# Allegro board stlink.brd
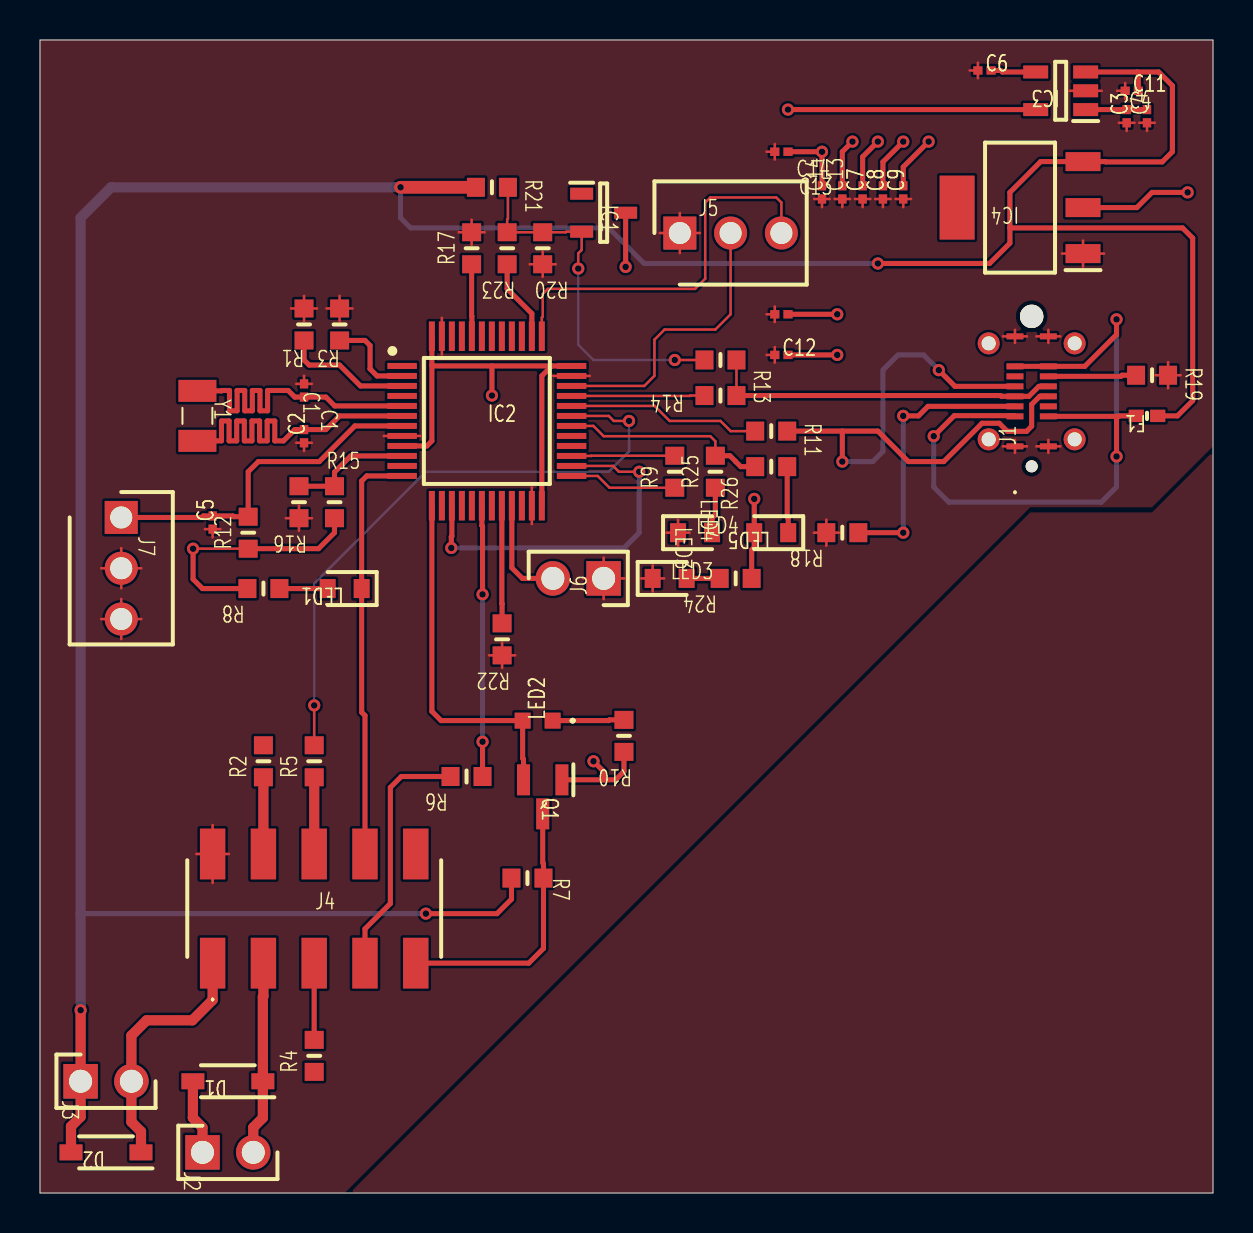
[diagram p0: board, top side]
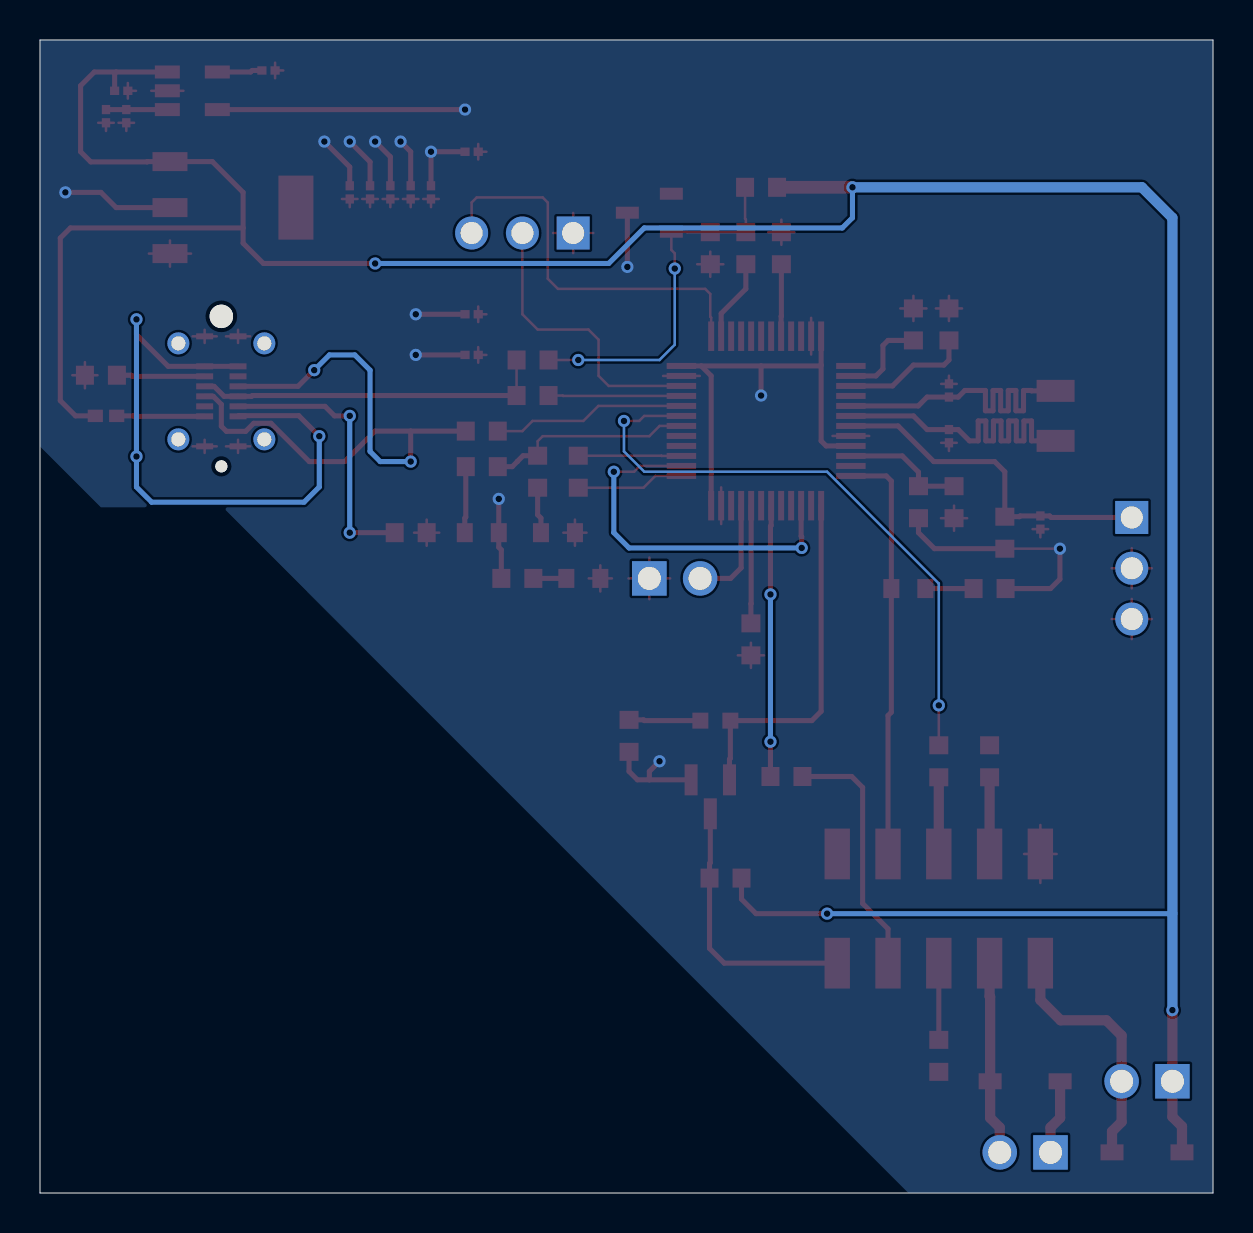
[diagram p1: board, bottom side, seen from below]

Outline 58.67 x 57.66 mm; copper layers: TOP, BOTTOM. Coordinates in mm from the lower left corner of the outline.
Outline path: 0,57.66 0,0 58.67,0 58.67,57.66 0,57.66

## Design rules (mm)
constraint set DEFAULT: min track width 0.127
net group DN: nets DN USB_DM
net group RESET: nets N06427 RESET
net group SWO: nets N06435 SWO
net group +5V: nets DP N06887 N27475 USB_DP
net group LED_LINK: nets LED_LINK N09917 N09921

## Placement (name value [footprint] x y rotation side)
C1  20p  [CAPC0603X33N]  13.21 40.13 270 top
C2  20p  [CAPC0603X33N]  13.21 37.85 90 top
C3  1u  [CAPC0603X33N]  54.36 53.85 90 top
C4  100n  [CAPC0603X33N]  55.37 53.85 90 top
C5  100n  [CAPC0603X33N]  8.64 33.53 90 top
C6  22n  [CAPC0603X33N]  47.24 56.13 0 top
C7  10u  [CAPC0603X33N]  41.15 50.04 90 top
C8  100n  [CAPC0603X33N]  42.16 50.04 90 top
C9  20p  [CAPC0603X33N]  43.18 50.04 90 top
C10  20p  [CAPC0603X33N]  37.08 43.94 0 top
C11  20p  [CAPC0603X33N]  54.61 55.12 0 top
C12  100n  [CAPC0603X33N]  37.08 41.91 0 top
C13  100n  [CAPC0603X33N]  40.13 50.04 90 top
C14  100n  [CAPC0603X33N]  39.12 50.04 90 top
C15  100n  [CAPC0603X33N]  37.08 52.07 0 top
D1  MBR0520LT3G  [SOD3716X135N]  9.4 5.59 180 top
D2  MBR0520LT3G  [SOD3716X135N]  3.3 2.03 180 top
F1  SF-0402F050-2  [FUSC1005X40N]  55.37 38.86 180 top
IC1  MMS9013-L-TP  [SOT95P237X125-3N]  28.19 49.02 0 top
IC2  STM32F103CBT6  [QFP50P900X900X160-48N]  22.35 38.61 0 top
IC3  RT9193-33GB  [SOT94P279X130-5N]  51.05 55.12 180 top
IC4  LM1117MPX-33NOPB  [SOT230P700X180-4N]  49.02 49.28 180 top
J1  219320-0001  [2193200001]  48.77 37.34 90 top
J2  JUMPER  [HDRV2W67P254_2X1_254X483X858P]  8.13 2.03 270 top
J3  JUMPER  [HDRV2W67P254_2X1_254X483X858P]  2.03 5.59 270 top
J4  95278-401A10LF  [95278401A10LF]  13.72 14.22 0 top
J5  69167-103  [SHDR3W64P0X254_1X3_762X516X980P]  32 48.01 0 top
J6  JUMPER  [HDRV2W67P254_2X1_254X483X858P]  28.19 30.73 90 top
J7  69167-103  [SHDR3W64P0X254_1X3_762X516X980P]  4.06 33.78 270 top
LED1  SM0603GCL  [LEDC1608X60N]  15.24 30.23 180 top
LED2  -  [SM0603SRC]  24.89 23.62 90 top
LED3  SM0603GCL  [LEDC1608X60N]  31.5 30.73 0 top
LED4  SM0603GCL  [LEDC1608X60N]  32.77 33.02 0 top
LED5  SM0603GCL  [LEDC1608X60N]  36.58 33.02 180 top
Q1  2N7002  [SOT96P240X120-3N]  25.15 19.81 270 top
R1  10K  [RESC1608X55N]  13.21 43.43 270 top
R2  22  [RESC1608X55N]  11.18 21.59 90 top
R3  10K  [RESC1608X55N]  14.99 43.43 270 top
R4  22  [RESC1608X55N]  13.72 6.86 90 top
R5  22  [RESC1608X55N]  13.72 21.59 90 top
R6  22  [RESC1608X55N]  21.34 20.83 180 top
R7  1K  [RESC1608X55N]  24.38 15.75 0 top
R8  1K  [RESC1608X55N]  11.18 30.23 180 top
R9  100  [RESC1608X55N]  31.75 36.07 90 top
R10  1K  [RESC1608X55N]  29.21 22.86 270 top
R11  0  [RESC1608X55N]  36.58 38.1 0 top
R12  100K  [RESC1608X55N]  10.41 33.02 90 top
R13  0  [RESC1608X55N]  34.04 39.88 0 top
R14  1K5  [RESC1608X55N]  34.04 41.66 180 top
R15  4K7  [RESC1608X55N]  14.73 34.54 90 top
R16  4K7  [RESC1608X55N]  12.95 34.54 270 top
R17  10K  [RESC1608X55N]  21.59 47.24 90 top
R18  5.1K  [RESC1608X55N]  40.13 33.02 180 top
R19  5.1K  [RESC1608X55N]  55.63 40.89 0 top
R20  36K  [RESC1608X55N]  25.15 47.24 270 top
R21  10K  [RESC1608X55N]  22.61 50.29 0 top
R22  10K  [RESC1608X55N]  23.11 27.69 270 top
R23  100  [RESC1608X55N]  23.37 47.24 270 top
R24  10K  [RESC1608X55N]  34.8 30.73 180 top
R25  1K  [RESC1608X55N]  33.78 36.07 90 top
R26  1K  [RESC1608X55N]  36.58 36.32 180 top
Y1  ABS07-32  [ABS07]  7.87 38.86 270 top

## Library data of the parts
C1-C15 = GRM033D70E105ME15D
D1 D2 = MBR0520LT3G
F1 = SF-0402F050-2
IC1 = MMS9013-L-TP
IC2 = STM32F103CBT6
IC3 = RT9193-33GB
IC4 = LM1117MPX-33NOPB
J1 = 219320-0001
J2 J3 J6 = 67996-100HLF
J4 = 95278-401A10LF
J5 J7 = 69167-103
LED1 LED3-LED5 = SM0603GCL
LED2 = SM0603SRC
Q1 = 2N7002
R1-R26 = CR0603-F_-1R00ELF
Y1 = ABS07-32.768KHZ-T

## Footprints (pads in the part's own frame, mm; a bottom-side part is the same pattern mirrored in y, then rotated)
95278401A10LF
  rect 1.27x2.54 smd: 1(-5.08,-2.73) 2(-5.08,2.73) 3(-2.54,-2.73) 4(-2.54,2.73) 5(0,-2.73) 6(0,2.73) 7(2.54,-2.73) 8(2.54,2.73) 9(5.08,-2.73) 10(5.08,2.73)
2193200001
  round 0.6 hole 0.6 unplated: (-1,-0.835)
  round 1.17 hole 1.17 unplated: (6.5,-0.835)
  rect 0.3x0.85 smd: A1(0,0) A4(1.5,0) A5(2,0) A6(2.5,0) A7(3,0) A8(3.5,0) A9(4,0) A12(5.5,0) B1(5.5,-1.67) B4(4,-1.67) B5(3.5,-1.67) B6(3,-1.67) B7(2.5,-1.67) B8(2,-1.67) B9(1.5,-1.67) B12(0,-1.67)
  round 1.1 hole 0.7: MH3(0.35,1.315) MH4(5.15,1.315) MH5(5.15,-2.985) MH6(0.35,-2.985)
ABS07
  rect 1.1x1.9 smd: 1(-1.25,0) 2(1.25,0)
CAPC0603X33N
  rect 0.46x0.42 smd: 1(-0.33,0) 2(0.33,0)
FUSC1005X40N
  rect 0.76x0.62 smd: 1(-0.535,0) 2(0.535,0)
HDRV2W67P254_2X1_254X483X858P
  rect 1.725x1.725 hole 1.15: 1(0,0)
  round 1.725 hole 1.15: 2(0,2.54)
LEDC1608X60N
  rect 0.8x0.95 smd: 1(-0.85,0) 2(0.85,0)
QFP50P900X900X160-48N
  rect 1.475x0.3 smd: 1(-4.238,2.75) 2(-4.238,2.25) 3(-4.238,1.75) 4(-4.238,1.25) 5(-4.238,0.75) 6(-4.238,0.25) 7(-4.238,-0.25) 8(-4.238,-0.75) 9(-4.238,-1.25) 10(-4.238,-1.75) 11(-4.238,-2.25) 12(-4.238,-2.75) 25(4.238,-2.75) 26(4.238,-2.25) 27(4.238,-1.75) 28(4.238,-1.25) 29(4.238,-0.75) 30(4.238,-0.25) 31(4.238,0.25) 32(4.238,0.75) 33(4.238,1.25) 34(4.238,1.75) 35(4.238,2.25) 36(4.238,2.75)
  rect 0.3x1.475 smd: 13(-2.75,-4.238) 14(-2.25,-4.238) 15(-1.75,-4.238) 16(-1.25,-4.238) 17(-0.75,-4.238) 18(-0.25,-4.238) 19(0.25,-4.238) 20(0.75,-4.238) 21(1.25,-4.238) 22(1.75,-4.238) 23(2.25,-4.238) 24(2.75,-4.238) 37(2.75,4.238) 38(2.25,4.238) 39(1.75,4.238) 40(1.25,4.238) 41(0.75,4.238) 42(0.25,4.238) 43(-0.25,4.238) 44(-0.75,4.238) 45(-1.25,4.238) 46(-1.75,4.238) 47(-2.25,4.238) 48(-2.75,4.238)
RESC1608X55N
  rect 0.9x0.95 smd: 1(-0.8,0) 2(0.8,0)
SHDR3W64P0X254_1X3_762X516X980P
  rect 1.65x1.65 hole 1.1: 1(0,0)
  round 1.65 hole 1.1: 2(2.54,0) 3(5.08,0)
SM0603SRC
  rect 0.8x0.8 smd: 1(0,-0.75) 2(0,0.75)
SOD3716X135N
  rect 1.15x0.8 smd: 1(-1.75,0) 2(1.75,0)
SOT94P279X130-5N
  rect 1.25x0.65 smd: 1(-1.25,0.94) 2(-1.25,0) 3(-1.25,-0.94) 4(1.25,-0.94) 5(1.25,0.94)
SOT95P237X125-3N
  rect 1.15x0.6 smd: 1(-1.1,0.95) 2(-1.1,-0.95) 3(1.1,0)
SOT96P240X120-3N
  rect 1.55x0.65 smd: 1(-0.85,0.96) 2(-0.85,-0.96) 3(0.85,0)
SOT230P700X180-4N
  rect 1.75x0.95 smd: 1(-3.15,2.3) 2(-3.15,0) 3(-3.15,-2.3)
  rect 1.75x3.2 smd: 4(3.15,0)

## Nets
+3V3: C7.2 C8.2 C9.2 C10.2 C12.2 C13.2 C14.2 C15.2 IC1.3 IC2.9 IC2.24 IC2.36 IC2.48 IC3.5(\VOUT\) IC4.2 LED5.2 Q1.1 R8.2 R10.2 R12.1 R15.1 R24.1
+5V: C11.2 D2.2 F1.1 IC3.3 IC4.3 J3.1 R7.1 R21.1
GND: C1.1 C2.1 C3.1 C4.1 C5.1 C6.1 C7.1 C8.1 C9.1 C10.1 C11.1 C12.1 C13.1 C14.1 C15.1 IC2.8 IC2.23 IC2.35 IC2.47(\VSS_3\) IC3.2 IC4.1 J1.A1 J1.A12 J1.B1 J1.B12 J4.2 J5.1 J6.1 J7.2 J7.3 LED3.1(\K\) LED4.1(\K\) R1.1 R3.1 R16.2 R17.2 R18.2 R19.2 R20.2 R22.2
VBAT: IC2.1
BOOT_0: IC2.44 R17.1
BOOT_1: IC2.20 R22.1
DN: J1.A7 J1.B7 R11.2
DP: J1.A6(\[DP1\) J1.B6 R13.2 R14.1
FUSE: F1.2 J1.A4 J1.A9 J1.B4 J1.B9
LED_LINK: IC2.30 R25.2 R26.2
PA0: IC2.10 R15.2 R16.1
RESET: IC2.18 R6.1
RST: C5.2 IC2.7 J7.1 R12.2
RX: IC2.13 LED2.2(\K\) Q1.2(\S\)
SWCLK: IC2.15 IC2.26 R4.1
SWCLK_IN: IC2.37 J5.3
SWDIO: IC2.25 R2.2 R9.1
SWDIO_IN: IC2.34 J5.2
SWO: IC2.31 R5.2
TX: IC2.12 J4.8 LED1.1(\K\)
USB_DM: IC2.32 R11.1
USB_DP: IC2.33 R13.1
USB_RENUM: IC2.38 R23.2
N00368: IC2.2 R3.2
N00410: IC2.3 R1.2
N00775: C1.2 IC2.5 Y1.1
N00782: C2.2 IC2.6 Y1.2
N01382: IC2.21 J6.2
N02734: IC2.27 R9.2
N04880: D2.1(\K\) J3.2 J4.1
N05760: D1.2 J2.1
N05764: D1.1(\K\) J2.2 J4.3
N06309: J4.4 R2.1
N06427: J4.7 R6.2
N06431: J4.5 R4.2
N06435: J4.6 R5.1
N06707: LED1.2 R8.1
N06887: J4.9 Q1.3 R7.2
N07180: LED2.1 R10.1
N08768: LED3.2 R24.2
N09917: LED4.2 R25.1
N09921: LED5.1(\K\) R26.1
N11997: C3.2 C4.2 IC3.1
N13004: C6.2 IC3.4
N27475: IC1.2(\E\) R14.2 R20.1 R21.2 R23.1
N30478: J1.B5 R19.1
N30510: J1.A5 R18.1

Pads without a net: IC1 1; IC2 4 11 14 16 17 19 22 28 29 39 40 41 42 43 45 46; IC4 4; J1 A8 B8 MH3 MH4 MH5 MH6; J4 10

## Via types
v1: diameter 0.61, hole 0.33, TOP to BOTTOM, 33 vias

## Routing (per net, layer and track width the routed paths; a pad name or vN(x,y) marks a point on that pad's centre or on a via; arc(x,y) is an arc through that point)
+3V3: length 83.8
  TOP w0.127: R12.1 v1(7.66,32.22)
  TOP w0.254: C7.2 41.15,51.82 v1(41.91,52.58) ; IC2.24 25.1,40.86 25.6,41.36 ; 22.61,41.36 v1(22.61,39.88) ; 22.61,41.36 25.6,41.36 ; 22.61,41.36 19.65,41.36 19.6,41.4 ; 25.6,41.36 IC2.36 ; 28.19,20.66 28.19,21.08 v1(27.69,21.59) ; 28.19,20.66 Q1.1 ; 28.19,20.66 28.79,20.66 29.21,21.08 R10.2 ; IC4.2 54.86,49.28 55.63,50.04 v1(57.4,50.04) ; v1(43.18,52.58) 42.16,51.56 C8.2 ; IC3.5 v1(37.41,54.18) ; IC1.3 v1(29.29,46.31) ; R24.1 35.6,32.16 35.73,32.29 LED5.2 v1(35.73,34.71) ; v1(44.45,52.58) 43.18,51.31 C9.2 ; R8.2 8.13,30.23 7.66,30.7 v1(7.66,32.22) ; R12.1 13.93,32.22 14.73,33.02 R15.1 ; C10.2 v1(39.88,43.94) ; 19.6,41.4 19.6,37.61 19.35,37.36 IC2.9 ; 19.6,41.4 IC2.48 ; C13.2 40.13,52.07 v1(40.64,52.58) ; C12.2 v1(39.88,41.91) ; C14.2 v1(39.12,52.07) C15.2
+5V: length 163.6
  TOP w0.254: 54.86,56.06 55.96,56.06 56.64,55.37 56.64,52.07 56.13,51.56 53.32,51.56 53.3,51.58 IC4.3 50.05,51.58 48.51,50.04 48.51,48.26 ; 54.86,56.06 54.94,55.98 C11.2 ; 54.86,56.06 IC3.3 ; F1.1 56.9,38.86 57.66,39.62 57.66,47.75 57.15,48.26 48.51,48.26 ; 48.51,48.26 48.51,47.5 47.5,46.48 v1(41.91,46.48) ; R7.1 23.58,14.69 22.86,13.97 v1(19.3,13.97)
  TOP w0.512: v1(2.03,9.14) J3.1 2.03,3.81 1.55,3.33 D2.2
  TOP w0.635: R21.1 v1(18.03,50.29)
  BOTTOM w0.254: v1(19.3,13.97) 2.03,13.97 ; v1(41.91,46.48) 30.23,46.48 28.45,48.26 18.54,48.26 18.03,48.77 v1(18.03,50.29)
  BOTTOM w0.512: v1(2.03,9.14) 2.03,48.77 3.56,50.29 v1(18.03,50.29)
GND: length 83.7
  TOP w0.127: 46.51,56.13 C6.1 ; C6.1 46.91,55.75 ; C6.1 46.91,56.52 ; 42.16,49.3 C8.1 ; C8.1 42.55,49.71 ; C8.1 41.78,49.71 ; 36.75,43.55 C10.1 ; C10.1 36.35,43.94 ; C10.1 36.75,44.33 ; 24.6,33.45 IC2.23 24.6,35.29 ; 53.11,55.12 IC3.2 51.5,55.12 ; 30.65,30.08 LED3.1 ; LED3.1 31.22,30.73 ; LED3.1 30.65,31.39 ; LED3.1 30.07,30.73 ; 39.12,49.3 C14.1 ; C14.1 38.73,49.71 ; C14.1 39.5,49.71 ; J1.B1 50.44,43.17 ; J1.B1 50.44,42.51 ; J1.B1 51.04,42.84 ; J1.B1 49.83,42.84 ; R1.1 13.86,44.23 ; R1.1 13.21,44.86 ; R1.1 13.21,43.61 ; R1.1 12.55,44.23 ; J7.3 5.07,28.7 ; J7.3 3.06,28.7 ; J7.3 4.06,27.7 ; J7.3 4.06,29.7 ; IC4.1 52.17,47.63 ; IC4.1 52.17,46.32 ; IC4.1 51.12,46.98 ; IC4.1 53.23,46.98 ; C15.1 36.75,52.46 ; C15.1 36.75,51.68 ; C15.1 36.35,52.07 ; C1.1 13.21,40.87 ; C1.1 12.82,40.46 ; C1.1 13.6,40.46 ; J1.B12 51.04,37.34 ; J1.B12 50.44,37.67 ; J1.B12 49.83,37.34 ; J1.B12 50.44,37.01 ; R20.2 25.15,47.07 ; R20.2 25.8,46.44 ; R20.2 25.15,45.82 ; R20.2 24.49,46.44 ; 28.19,29.69 J6.1 ; J6.1 27.15,30.73 ; J6.1 29.23,30.73 ; J6.1 28.19,31.77 ; 39.33,32.37 R18.2 ; R18.2 39.96,33.02 ; R18.2 38.7,33.02 ; R18.2 39.33,33.67 ; J4.2 8.64,18.4 ; J4.2 7.82,16.95 ; J4.2 8.64,15.51 ; J4.2 9.45,16.95 ; 13.21,37.11 C2.1 ; C2.1 13.6,37.52 ; C2.1 12.82,37.52 ; 36.75,41.52 C12.1 ; C12.1 36.75,42.3 ; C12.1 36.35,41.91 ; C7.1 41.54,49.71 ; C7.1 40.76,49.71 ; C7.1 41.15,49.3 ; 55.37,53.11 C4.1 ; C4.1 55.76,53.52 ; C4.1 54.98,53.52 ; LED4.1 32.49,33.02 ; LED4.1 31.92,33.67 ; LED4.1 31.34,33.02 ; LED4.1 31.92,32.37 ; 39.74,49.71 C13.1 ; C13.1 40.13,49.3 ; C13.1 40.52,49.71 ; 8.25,33.2 C5.1 ; C5.1 9.02,33.2 ; C5.1 8.64,32.79 ; 55.8,40.89 R19.2 ; R19.2 56.43,41.55 ; R19.2 56.43,40.24 ; R19.2 57.05,40.89 ; J1.A12 48.77,43.17 ; J1.A12 48.16,42.84 ; J1.A12 49.37,42.84 ; J1.A12 48.77,42.51 ; 43.18,49.3 C9.1 ; C9.1 43.57,49.71 ; C9.1 42.79,49.71 ; 14.33,44.23 R3.1 ; R3.1 14.99,44.86 ; R3.1 15.64,44.23 ; R3.1 14.99,43.61 ; R17.2 21.59,48.67 ; R17.2 20.94,48.04 ; R17.2 22.24,48.04 ; R17.2 21.59,47.42 ; J5.1 33.01,48.01 ; J5.1 31,48.01 ; J5.1 32,47 ; J5.1 32,49.01 ; 3.06,31.24 J7.2 ; J7.2 5.07,31.24 ; J7.2 4.06,32.25 ; J7.2 4.06,30.24 ; 20.1,41.93 IC2.47 20.1,43.76 ; 53.87,55.12 C11.1 ; C11.1 54.28,55.51 ; C11.1 54.28,54.73 ; R22.2 23.11,27.51 ; R22.2 23.77,26.89 ; R22.2 22.46,26.89 ; R22.2 23.11,26.26 ; 17.2,37.86 IC2.8 19.03,37.86 ; C3.1 54.74,53.52 ; C3.1 53.97,53.52 ; C3.1 54.36,53.11 ; 48.77,37.01 J1.A1 ; J1.A1 48.16,37.34 ; J1.A1 48.77,37.67 ; J1.A1 49.37,37.34 ; R16.2 12.95,34.37 ; R16.2 12.95,33.12 ; R16.2 13.61,33.74 ; R16.2 12.3,33.74 ; 27.51,40.86 IC2.35 25.67,40.86
BOOT_0: length 3.6
  TOP w0.254: R17.1 21.59,43.85 21.6,43.84 IC2.44
BOOT_1: length 5.9
  TOP w0.254: R22.1 23.11,29.46 23.1,29.48 IC2.20
DN: length 31.4
  TOP w0.254: J1.B7 50,39.84 49.6,39.44 49.6,38.34 49.35,38.09 48.39,38.09 47.98,38.49 47.12,38.49 45.2,36.58 43.43,36.58 41.91,38.1 40.13,38.1 ; 40.13,38.1 R11.2 ; 40.13,38.1 v1(40.13,36.58) ; v1(44.96,41.15) 45.77,40.34 J1.A7
  BOTTOM w0.254: v1(44.96,41.15) 44.2,41.91 42.93,41.91 42.16,41.15 42.16,37.08 41.66,36.58 v1(40.13,36.58)
DP: length 17.6
  TOP w0.127: R14.1 R13.2
  TOP w0.254: J1.B6 49.96,40.34 49.46,39.84 J1.A6 48.09,39.84 48.05,39.88 R13.2
FUSE: length 38.1
  TOP w0.254: 53.85,38.84 J1.B9 ; 53.85,38.84 53.96,38.84 53.98,38.86 F1.2 ; 53.85,38.84 v1(53.85,36.83) ; J1.A9 J1.B4 52.26,41.34 53.85,42.93 v1(53.85,43.69) ; J1.A4 48.73,38.87 45.73,38.87 v1(44.7,37.85)
  BOTTOM w0.254: v1(53.85,43.69) v1(53.85,36.83) 53.85,35.31 53.09,34.54 45.47,34.54 44.7,35.31 v1(44.7,37.85)
LED_LINK: length 10.5
  TOP w0.127: R25.2 33.78,37.59 33.53,37.85 28.19,37.85 27.68,38.36 IC2.30
  TOP w0.254: R25.2 34.51,36.87 34.79,36.59 34.79,36.58 35.05,36.32 R26.2
PA0: length 6.2
  TOP w0.254: R16.1 R15.2 14.73,36.05 15.54,36.86 IC2.10
RESET: length 13.6
  TOP w0.254: v1(22.14,29.93) 22.14,33.34 22.1,33.38 IC2.18 ; R6.1 v1(22.14,22.57)
  BOTTOM w0.254: v1(22.14,22.57) v1(22.14,29.93)
RST: length 17.3
  TOP w0.254: J7.1 8.1,33.78 8.17,33.86 C5.2 9.65,33.86 9.68,33.82 R12.2 10.41,36.07 10.92,36.58 13.97,36.58 15.75,38.36 IC2.7
RX: length 18
  TOP w0.254: Q1.2 24.19,21.69 24.14,21.73 LED2.2 20.07,23.62 19.6,24.09 IC2.13
SWCLK: length 18.4
  TOP w0.127: v1(29.97,36.07) 28.96,36.07 28.67,36.36 IC2.26
  TOP w0.254: v1(20.57,32.26) 20.57,32.82 20.6,32.84 IC2.15
  BOTTOM w0.254: v1(29.97,36.07) 29.97,33.02 29.21,32.26 v1(20.57,32.26)
SWCLK_IN: length 19.9
  TOP w0.127: IC2.37 25.1,43.77 25.15,43.82 25.15,44.96 25.4,45.21 32.77,45.21 33.27,45.72 33.27,49.53 33.53,49.78 36.83,49.78 37.08,49.53 J5.3
SWDIO: length 5.4
  TOP w0.127: IC2.25 27.9,35.86 28.49,35.27 R9.1
SWDIO_IN: length 14.6
  TOP w0.127: IC2.34 30.23,40.36 30.73,40.87 30.73,42.67 31.24,43.18 33.78,43.18 34.54,43.94 J5.2
SWO: length 31.1
  TOP w0.127: v1(29.46,38.61) 28.7,38.61 28.45,38.86 IC2.31 ; v1(13.72,24.38) R5.2
  BOTTOM w0.127: v1(29.46,38.61) 29.46,37.08 28.45,36.07 19.3,36.07 13.72,30.48 v1(13.72,24.38)
TX: length 20.8
  TOP w0.254: IC2.12 16.34,35.86 16.09,35.6 LED1.1 16.09,24.04 16.26,23.88 J4.8
USB_DM: length 9.7
  TOP w0.127: R11.1 34.54,38.1 34.04,38.61 31.5,38.61 30.75,39.36 IC2.32
USB_DP: length 6.7
  TOP w0.127: R13.1 32.53,39.88 32.51,39.86 IC2.33
USB_RENUM: length 4.1
  TOP w0.254: R23.2 23.37,45.21 24.6,43.98 IC2.38
N00368: length 4.6
  TOP w0.254: IC2.2 16.86,40.86 16.51,41.21 16.51,42.38 16.26,42.63 R3.2
N00410: length 6.4
  TOP w0.254: R1.2 13.21,41.66 13.46,41.4 14.99,41.4 16.03,40.36 IC2.3
N00775: length 16.7
  TOP w0.254: Y1.1 9.08,40.11 9.1,40.13 9.48,40.13 9.48,39.12 9.86,39.12 9.86,40.13 10.24,40.13 10.24,39.12 10.62,39.12 10.62,40.13 11,40.13 11,39.12 11.38,39.12 11.38,40.13 12.41,40.13 12.74,39.8 C1.2 14.3,39.8 14.74,39.36 IC2.5
N00782: length 18.7
  TOP w0.254: IC2.6 14.98,38.86 14.3,38.18 C2.2 12.74,38.18 12.18,37.61 11.74,37.61 11.74,38.61 11.36,38.61 11.36,37.61 10.98,37.61 10.98,38.61 10.6,38.61 10.6,37.61 10.22,37.61 10.22,38.61 9.84,38.61 9.84,37.61 9.46,37.61 9.46,38.61 9.08,38.61 9.08,37.61 Y1.2
N01382: length 5.4
  TOP w0.254: IC2.21 23.6,31.26 24.13,30.73 J6.2
N02734: length 5.2
  TOP w0.127: IC2.27 27.58,36.86 27.59,36.87 R9.2
N04880: length 12.7
  TOP w0.512: D2.1 5.05,3.08 4.57,3.56 J3.2 4.57,7.87 5.33,8.64 7.62,8.64 8.64,9.65 J4.1
N05760: length 3.8
  TOP w0.512: J2.1 8.13,3.28 7.65,3.76 D1.2
N05764: length 9.7
  TOP w0.512: J4.3 11.18,9.84 11.15,9.81 D1.1 11.15,3.76 10.67,3.28 J2.2
N06309: length 3.8
  TOP w0.512: R2.1 J4.4
N06427: length 12.5
  TOP w0.254: R6.2 18.07,20.83 17.53,20.28 17.53,14.48 16.26,13.21 J4.7
N06431: length 3.8
  TOP w0.254: R4.2 J4.5
N06435: length 3.8
  TOP w0.512: R5.1 J4.6
N06707: length 2.4
  TOP w0.254: LED1.2 R8.1
N06887: length 13.4
  TOP w0.254: J4.9 24.45,11.49 25.18,12.23 R7.2 25.18,16.48 25.15,16.51 Q1.3
N07180: length 3.6
  TOP w0.254: R10.1 28.48,23.66 28.44,23.62 LED2.1
N08768: length 1.7
  TOP w0.254: LED3.2 R24.2
N09917: length 2.3
  TOP w0.254: LED4.2 33.62,33.75 33.78,33.91 R25.1
N09921: length 3.3
  TOP w0.254: LED5.1 37.43,33.75 37.38,33.8 R26.1
N11997: length 3.1
  TOP w0.254: C4.2 C3.2 IC3.1
N13004: length 2.3
  TOP w0.254: C6.2 48.06,56.13 48.13,56.06 IC3.4
N27475: length 18.4
  TOP w0.127: R21.2 23.41,48.72 23.37,48.68 R23.1 R20.1 26.3,48.04 26.33,48.07 IC1.2 27.09,47.16 26.92,46.99 v1(26.92,46.23) ; R14.2 v1(31.75,41.66)
  BOTTOM w0.127: v1(31.75,41.66) 27.69,41.66 26.92,42.42 v1(26.92,46.23)
N30478: length 4.4
  TOP w0.254: J1.B5 54.07,40.84 54.12,40.89 R19.1
N30510: length 13.9
  TOP w0.254: J1.A5 44.42,39.34 43.94,38.86 v1(43.18,38.86) ; v1(43.18,33.02) R18.1
  BOTTOM w0.254: v1(43.18,38.86) v1(43.18,33.02)

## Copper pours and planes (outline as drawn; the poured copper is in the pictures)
+3V3 on BOTTOM: 0,57.66 0,0 15.24,0 49.53,34.29 55.63,34.29 58.67,37.34 58.67,57.66
+5V on TOP: 58.67,37.08 55.63,34.04 49.53,34.04 15.49,0 58.67,0
GND on TOP: 0,57.66 58.67,57.66 58.67,37.34 55.63,34.29 49.53,34.29 15.24,0 0,0

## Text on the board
User.Comments: WORLDSKILLS KAZAKHSTAN 2024
